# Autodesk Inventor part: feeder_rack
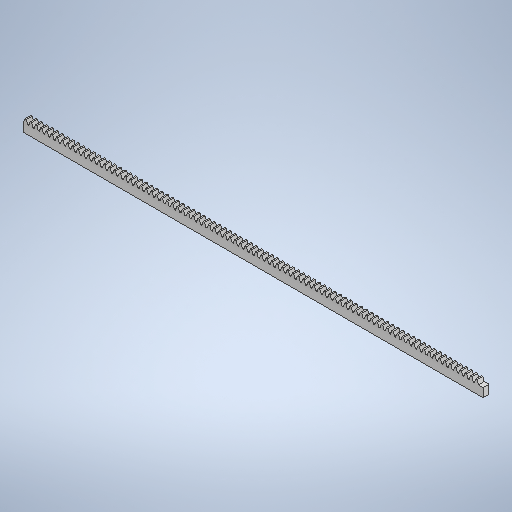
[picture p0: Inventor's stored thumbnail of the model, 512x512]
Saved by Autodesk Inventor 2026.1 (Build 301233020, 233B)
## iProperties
Company: meta-matic.com
Created: 2026-11
Part Number: feeder_rack
Material: Generic
Description: Rack Gear - meta-matic-generator 1.3
Document SubType Name: Modeling
Designer: alolo
Authority: META-MATIC-ID: 3dc0ee3cef1d
Density: 1 g/cm^3
Appearance: Default
Sending System: Open CASCADE
Preprocessor: meta-matic-generator 1.3
Title: Rack Gear_3dc0ee3cef1d
Author: Takahashi Mizuki @tkhsmz
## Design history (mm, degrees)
feature "Base1"
sketch "Sketch1"
  geometry: L1 (10, 10.5)-(0, 10.5) reference; L2 (0, 10.5)-(10, 10.5); L3 (10, 10.5)-(10, 0); L4 (10, 0)-(0, 0); L5 (0, 0)-(0, 10.5); 1 further point
  constraints: 8 end point, 2 parallel, 1 horizontal, 1 perpendicular
extrude "Extrusion1" join sketch "Sketch1" distance "d0" = 5; taper "d1" = 0 deg
sketch "Sketch2"
  geometry: L1 (0, 0)-(0, 10.5) reference; L2 (0, 0)-(551.637, 0) reference; L3 (551.637, 10.5)-(551.637, 0) reference; L4 (545.976, 10.5)-(551.637, 10.5) reference; L5 (544.338, 15)-(545.976, 10.5) reference; L6 (542.653, 15)-(544.338, 15) reference; L7 (541.015, 10.5)-(542.653, 15) reference; L8 (539.693, 10.5)-(541.015, 10.5) reference; L9 (538.055, 15)-(539.693, 10.5) reference; L10 (536.369, 15)-(538.055, 15) reference; L11 (534.732, 10.5)-(536.369, 15) reference; L12 (533.41, 10.5)-(534.732, 10.5) reference; L13 (531.772, 15)-(533.41, 10.5) reference; L14 (530.086, 15)-(531.772, 15) reference; L15 (528.448, 10.5)-(530.086, 15) reference; L16 (527.127, 10.5)-(528.448, 10.5) reference; L17 (525.489, 15)-(527.127, 10.5) reference; L18 (523.803, 15)-(525.489, 15) reference; L19 (522.165, 10.5)-(523.803, 15) reference; L20 (520.844, 10.5)-(522.165, 10.5) reference; L21 (519.206, 15)-(520.844, 10.5) reference; L22 (517.52, 15)-(519.206, 15) reference; L23 (515.882, 10.5)-(517.52, 15) reference; L24 (514.56, 10.5)-(515.882, 10.5) reference; L25 (512.922, 15)-(514.56, 10.5) reference; L26 (511.237, 15)-(512.922, 15) reference; L27 (509.599, 10.5)-(511.237, 15) reference; L28 (508.277, 10.5)-(509.599, 10.5) reference; L29 (506.639, 15)-(508.277, 10.5) reference; L30 (504.954, 15)-(506.639, 15) reference; L31 (503.316, 10.5)-(504.954, 15) reference; L32 (501.994, 10.5)-(503.316, 10.5) reference; L33 (500.356, 15)-(501.994, 10.5) reference; L34 (498.67, 15)-(500.356, 15) reference; L35 (497.033, 10.5)-(498.67, 15) reference; L36 (495.711, 10.5)-(497.033, 10.5) reference; L37 (494.073, 15)-(495.711, 10.5) reference; L38 (492.387, 15)-(494.073, 15) reference; L39 (490.749, 10.5)-(492.387, 15) reference; L40 (489.428, 10.5)-(490.749, 10.5) reference; L41 (487.79, 15)-(489.428, 10.5) reference; L42 (486.104, 15)-(487.79, 15) reference; L43 (484.466, 10.5)-(486.104, 15) reference; L44 (483.144, 10.5)-(484.466, 10.5) reference; L45 (481.507, 15)-(483.144, 10.5) reference; L46 (479.821, 15)-(481.507, 15) reference; L47 (478.183, 10.5)-(479.821, 15) reference; L48 (476.861, 10.5)-(478.183, 10.5) reference; L49 (475.223, 15)-(476.861, 10.5) reference; L50 (473.538, 15)-(475.223, 15) reference; L51 (471.9, 10.5)-(473.538, 15) reference; L52 (470.578, 10.5)-(471.9, 10.5) reference; L53 (468.94, 15)-(470.578, 10.5) reference; L54 (467.254, 15)-(468.94, 15) reference; L55 (465.617, 10.5)-(467.254, 15) reference; L56 (464.295, 10.5)-(465.617, 10.5) reference; L57 (462.657, 15)-(464.295, 10.5) reference; L58 (460.971, 15)-(462.657, 15) reference; L59 (459.333, 10.5)-(460.971, 15) reference; L60 (458.012, 10.5)-(459.333, 10.5) reference; L61 (456.374, 15)-(458.012, 10.5) reference; L62 (454.688, 15)-(456.374, 15) reference; L63 (453.05, 10.5)-(454.688, 15) reference; L64 (451.728, 10.5)-(453.05, 10.5) reference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; 1 further point
extrude "Extrusion2" cut sketch "Sketch2" distance "d2" = 3; taper "d3" = 0 deg
body "Solid1"
node "Projected Loop1"
